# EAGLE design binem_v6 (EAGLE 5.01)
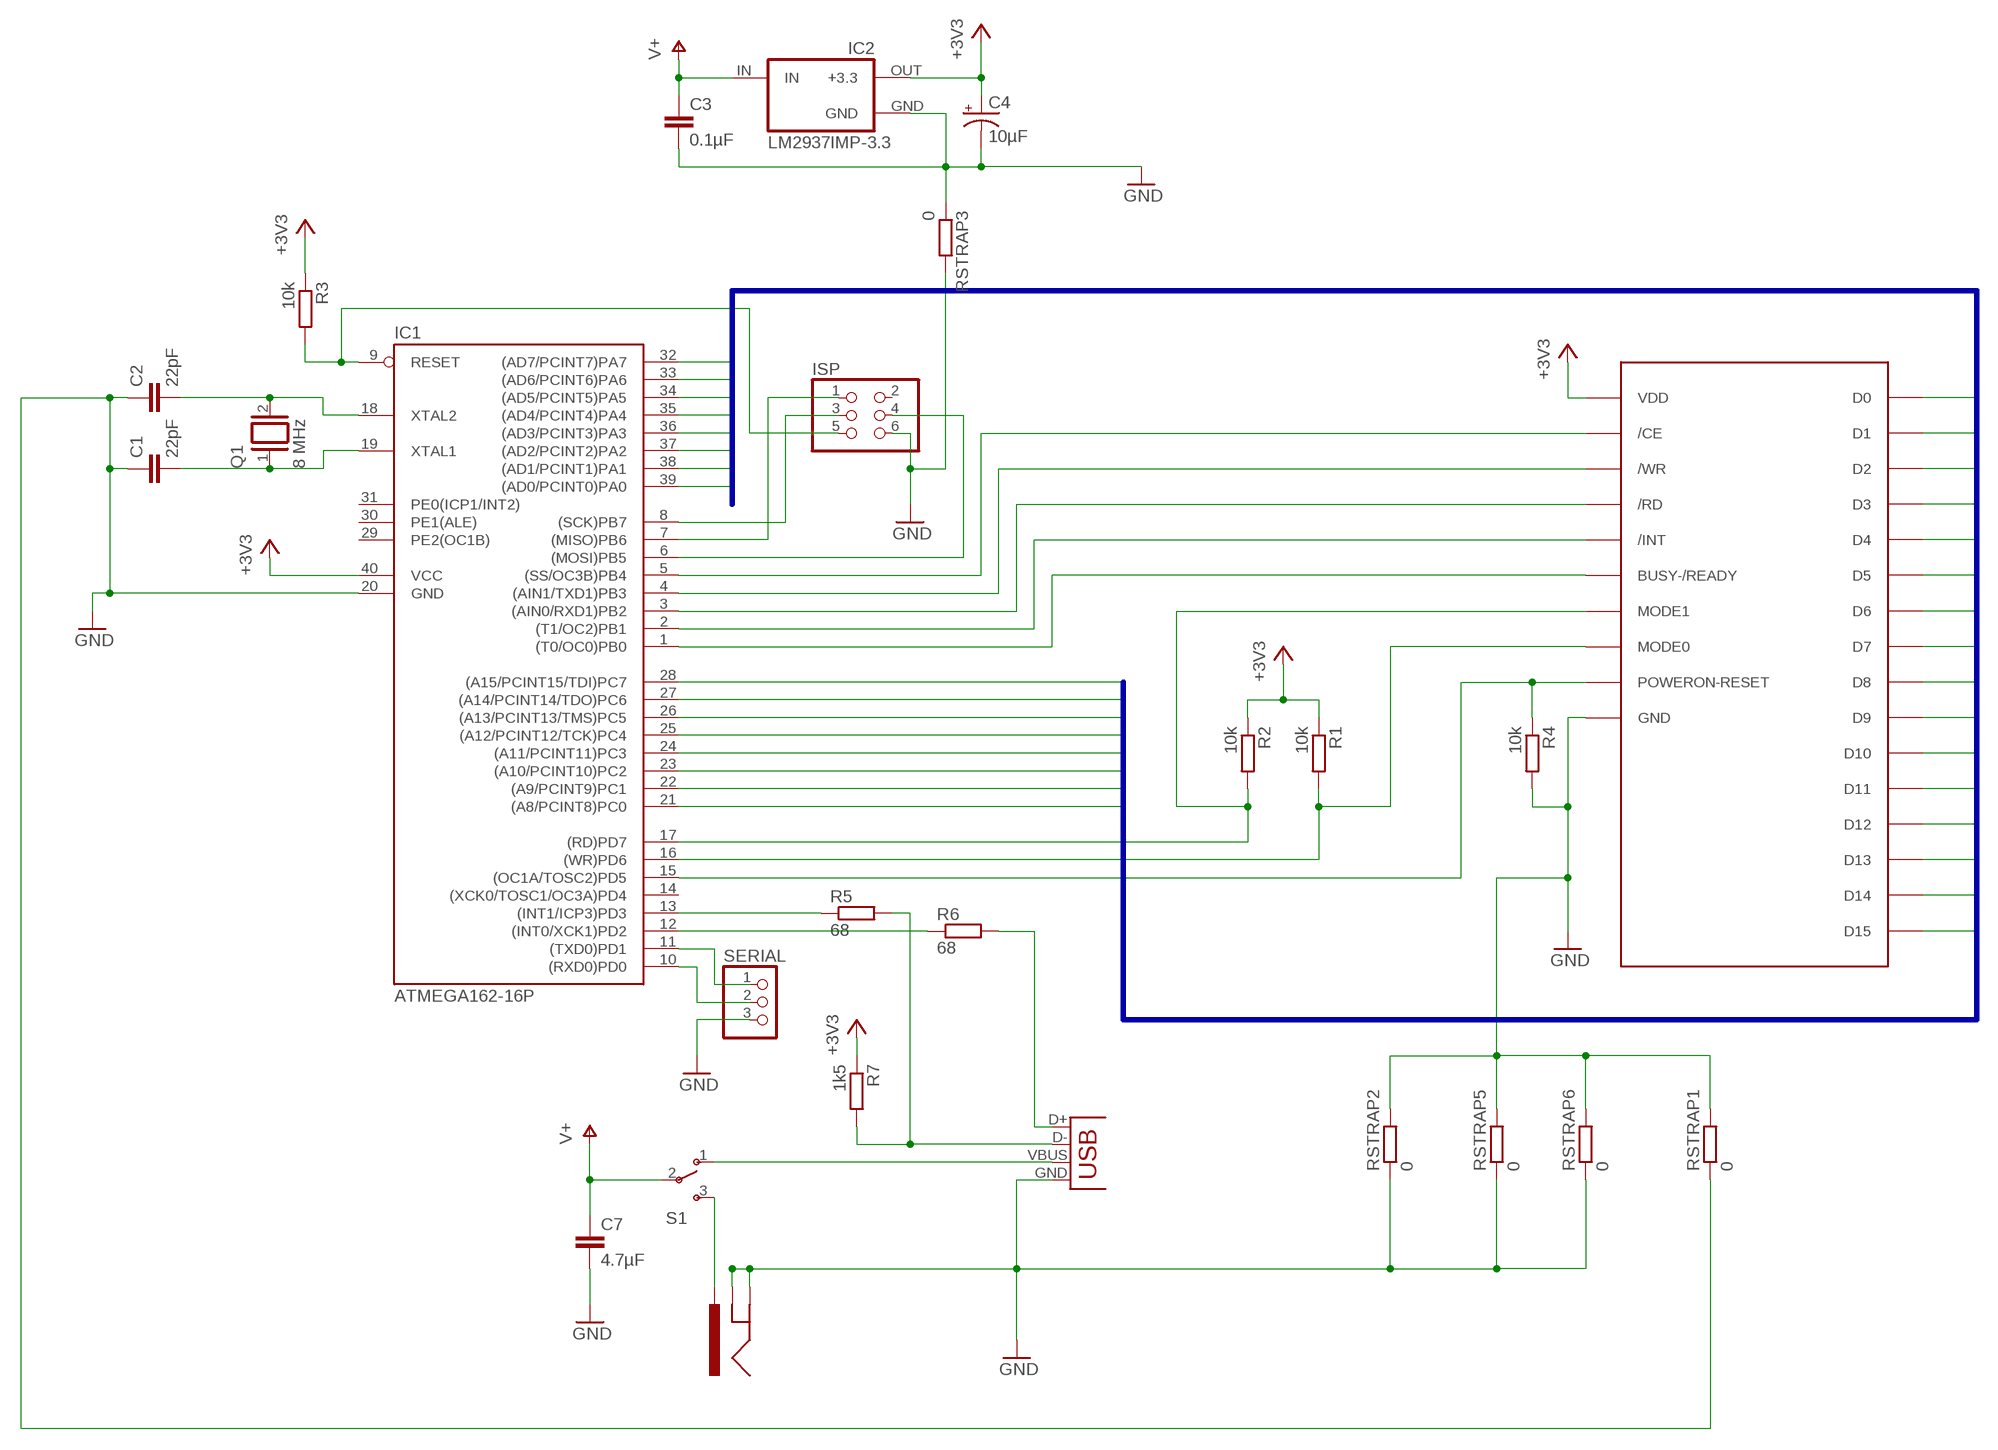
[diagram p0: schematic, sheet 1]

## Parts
C1  22pF  C-EUC1206  [C1206]
C2  22pF  C-EUC1206  [C1206]
C3  0.1µF  C-EUC1206  [C1206]
C4  10µF  CPOL-US175TMP-0808  [175TMP-0808]
C7  4.7µF  C-EUC1206  [C1206]
IC1  ATMEGA162-16P  [DIL40]
IC2  LM2937IMP-3.3  [SOT223]
ISP  PINHD-2X3  [2X03]
Q1  8 MHz  XTAL/S  [QS]
R1  10k  R-EU_R1206  [R1206]
R2  10k  R-EU_R1206  [R1206]
R3  10k  R-EU_R1206  [R1206]
R4  10k  R-EU_R1206  [R1206]
R5  68  R-EU_R1206  [R1206]
R6  68  R-EU_R1206  [R1206]
R7  1k5  R-EU_R1206  [R1206]
RSTRAP1  0  R-EU_R1206  [R1206]
RSTRAP2  0  R-EU_R1206  [R1206]
RSTRAP3  0  R-EU_R1206  [R1206]
RSTRAP5  0  R-EU_R1206  [R1206]
RSTRAP6  0  R-EU_R1206  [R1206]
S1  SWITCH-SPST  [SWITCH-SPST]
SERIAL  PINHD-1X3  [1X03]
U$1  BINEM-BK2300  [MOLEX-522713079]
U$3  POWER_JACKPTH  [POWER_JACK_PTH]
X1  USB  [USB-B-PTH]

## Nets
+3V3: C4.+ IC1.40(VCC) IC2.OUT(+3.3) R1.1 R2.1 R3.1 R7.1 U$1.P$10(VDD)
D0: IC1.39((AD0/PCINT0)PA0) U$1.P$11(D0)
D1: IC1.38((AD1/PCINT1)PA1) U$1.P$12(D1)
D2: IC1.37((AD2/PCINT2)PA2) U$1.P$13(D2)
D3: IC1.36((AD3/PCINT3)PA3) U$1.P$14(D3)
D4: IC1.35((AD4/PCINT4)PA4) U$1.P$15(D4)
D5: IC1.34((AD5/PCINT5)PA5) U$1.P$16(D5)
D6: IC1.33((AD6/PCINT6)PA6) U$1.P$17(D6)
D7: IC1.32((AD7/PCINT7)PA7) U$1.P$18(D7)
D8: IC1.28((A15/PCINT15/TDI)PC7) U$1.P$19(D8)
D9: IC1.27((A14/PCINT14/TDO)PC6) U$1.P$20(D9)
D10: IC1.26((A13/PCINT13/TMS)PC5) U$1.P$21(D10)
D11: IC1.25((A12/PCINT12/TCK)PC4) U$1.P$22(D11)
D12: IC1.24((A11/PCINT11)PC3) U$1.P$23(D12)
D13: IC1.23((A10/PCINT10)PC2) U$1.P$24(D13)
D14: IC1.22((A9/PCINT9)PC1) U$1.P$25(D14)
D15: IC1.21((A8/PCINT8)PC0) U$1.P$26(D15)
GND: C1.1 C2.1 C3.2 C4.- C7.2 IC1.20(GND) IC2.GND ISP.6 R4.2 RSTRAP1.1 RSTRAP1.2 RSTRAP2.1 RSTRAP2.2 RSTRAP3.1 RSTRAP3.2 RSTRAP5.1 RSTRAP5.2 RSTRAP6.1 RSTRAP6.2 SERIAL.3 U$1.P$1(GND) U$3.GND U$3.GNDBREAK X1.GND
MISO: IC1.7((MISO)PB6) ISP.1
MODE0: IC1.16((WR)PD6) R1.2 U$1.P$8(MODE0)
MODE1: IC1.17((RD)PD7) R2.2 U$1.P$7(MODE1)
MOSI: IC1.6((MOSI)PB5) ISP.4
N$1: IC1.13((INT1/ICP3)PD3) R5.1
N$2: R5.2 R7.2 X1.D-
N$3: IC1.12((INT0/XCK1)PD2) R6.1
N$4: R6.2 X1.D+
N$6: S1.3(S) U$3.PWR
N$7: IC1.5((SS/OC3B)PB4) U$1.P$2(/CE)
N$8: IC1.4((AIN1/TXD1)PB3) U$1.P$3(/WR)
N$9: IC1.3((AIN0/RXD1)PB2) U$1.P$4(/RD)
N$10: IC1.2((T1/OC2)PB1) U$1.P$5(/INT)
N$11: IC1.1((T0/OC0)PB0) U$1.P$6(BUSY-/READY)
N$12: IC1.10((RXD0)PD0) SERIAL.2
N$14: C2.2 IC1.18(XTAL2) Q1.2
N$15: C1.2 IC1.19(XTAL1) Q1.1
N$17: IC1.11((TXD0)PD1) SERIAL.1
POWERON-RESET: IC1.15((OC1A/TOSC2)PD5) R4.1 U$1.P$9(POWERON-RESET)
RESET: IC1.9(RESET) ISP.5 R3.2
SCK: IC1.8((SCK)PB7) ISP.3
V+: C3.1 C7.1 IC2.IN S1.2(P)
VUSB: S1.1(O) X1.VBUS
Unconnected: IC1.14((XCK0/TOSC1/OC3A)PD4) IC1.29(PE2(OC1B)) IC1.30(PE1(ALE)) IC1.31(PE0(ICP1/INT2)) ISP.2

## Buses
D[0..15]

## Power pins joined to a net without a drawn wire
GND: IC2.GND@(GND)

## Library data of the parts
C1-C3 C7 = rcl:C-EU: CAPACITOR, European symbol
C4 = rcl:CPOL-US: POLARIZED CAPACITOR, American symbol
IC1 = avr:ATMEGA162*P: MIKROCONTROLLER ATmega162 16kB Flash 2kB RAM 2 USARTS ATmega162 = 2,7-5,5V or ATmega162V = 1,8-5,5V
IC2 = lm2937:LM2937IMP-*: 400 and 500 mA Low Dropout Voltage Regulator NATIONAL SEMICONDUCTOR created by Peter.Hofmann@ph-tronic.de 10-2004 Rev.0
ISP = pinhead:PINHD-2X3: PIN HEADER
Q1 = special:XTAL/S: CRYSTAL
R1-R7 RSTRAP1-RSTRAP3 RSTRAP5 RSTRAP6 = rcl:R-EU_: RESISTOR, European symbol
S1 = SparkFunEagle-6-6-07:SWITCH-SPST: SPST Switch Simple slide switch. Spark Fun Electronics SKU : COM-00102
SERIAL = pinhead:PINHD-1X3: PIN HEADER
U$1 = perso:BINEM-BK2300
U$3 = SparkFunEagle-6-6-07:POWER_JACK: Power Jack This is the standard 5.5mm barrel jack for power. The PTH is the most common, proven, reliable, footprint. All others are experimental. The Slot footprint only works if the mill layer is transmitted to the PCB fab house so be warned. Spark Fun Electronics SKU : PRT-00119. Mating wall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
X1 = SparkFunEagle-6-6-07:USB: USB Connectors USB-B-PTH is fully proven SKU : PRT-00139 USB-miniB is fully proven SKU : PRT-00587 USB-A-H is throughly reviewed, but untested. Spark Fun Electronics SKU : PRT-00437 USB-B-SMT is throughly reviewed, but untested. Needs silkscreen touching up. USB-A-S has not been used/tested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

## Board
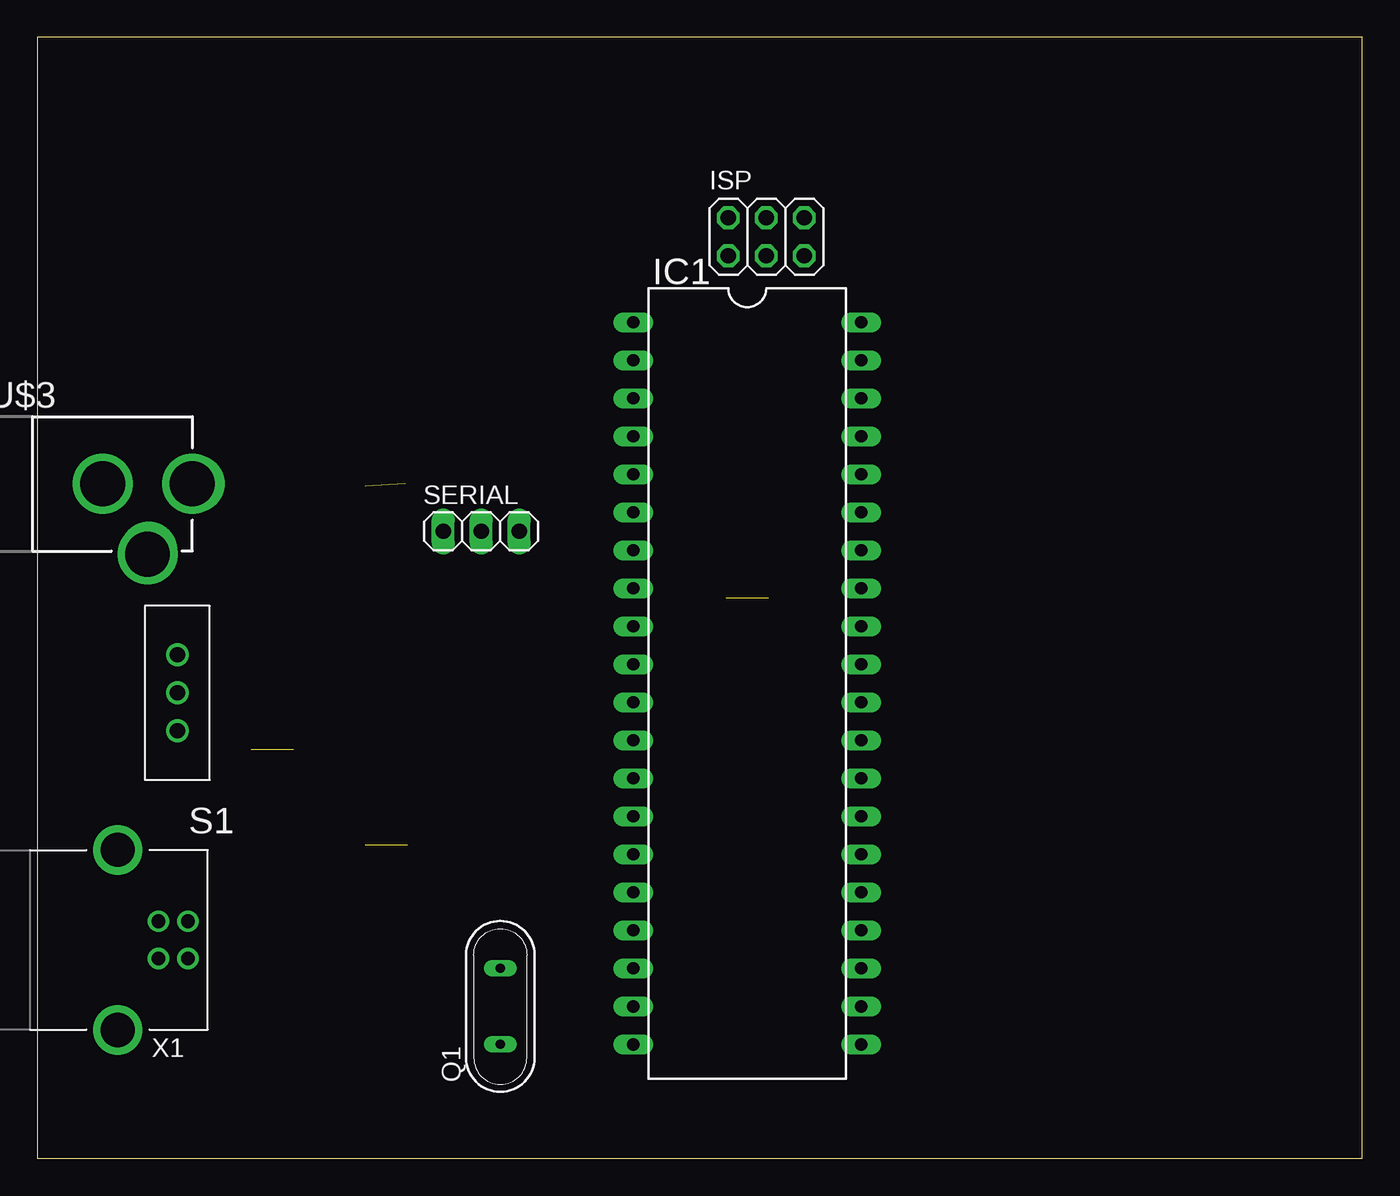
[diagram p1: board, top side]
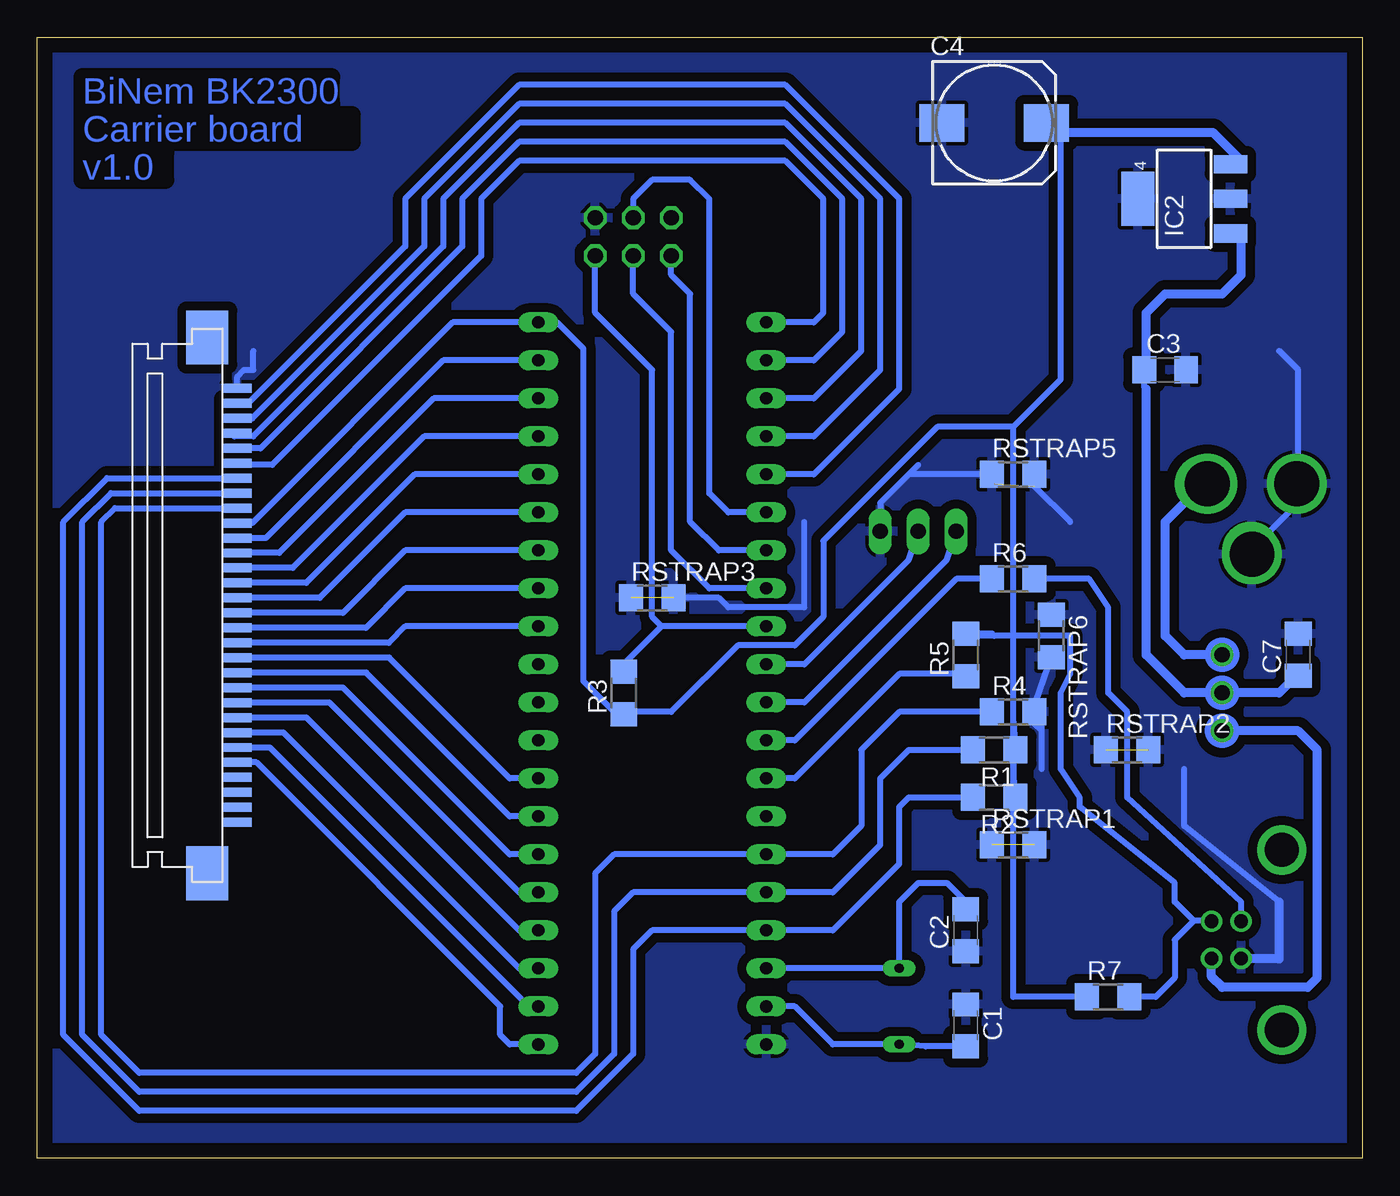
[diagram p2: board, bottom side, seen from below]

Size 88.57 x 74.92 mm. Coordinates in mm from the lower left corner, seen from the top.
Outline: 0,0 88.57,0 88.57,74.92 0,74.92 0,0
Copper layers (1*16): Top 0.035mm / dielectric 1.5mm / Bottom 0.035mm
Design rules "default *": minimum track width 10mil, minimum drill 24mil, track to track 8mil, track to pad 8mil, pad to pad 8mil, via to via 8mil, smd to smd 8mil, copper to edge 40mil, drill to drill 8mil, minimum pad ring 10mil, minimum via ring 8mil, stop-mask expansion 4mil, vias tented up to drill 0mil, thermal gap 10mil

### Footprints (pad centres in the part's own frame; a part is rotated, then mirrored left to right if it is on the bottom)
C1206 = smd 1.6 x 1.8: 1 -1.4,0; 2 1.4,0
175TMP-0808 = smd 3 x 2.5: + 3.5,0; - -3.5,0
DIL40 = drill 0.813 long: 1 -24.13,-7.62; 2 -21.59,-7.62; 3 -19.05,-7.62; 4 -16.51,-7.62; 5 -13.97,-7.62; 6 -11.43,-7.62; 7 -8.89,-7.62; 8 -6.35,-7.62; 9 -3.81,-7.62; 10 -1.27,-7.62; 11 1.27,-7.62; 12 3.81,-7.62; 13 6.35,-7.62; 14 8.89,-7.62; 15 11.43,-7.62; 16 13.97,-7.62; 17 16.51,-7.62; 18 19.05,-7.62; 19 21.59,-7.62; 20 24.13,-7.62; 21 24.13,7.62; 22 21.59,7.62; 23 19.05,7.62; 24 16.51,7.62; 25 13.97,7.62; 26 11.43,7.62; 27 8.89,7.62; 28 6.35,7.62; 29 3.81,7.62; 30 1.27,7.62; 31 -1.27,7.62; 32 -3.81,7.62; 33 -6.35,7.62; 34 -8.89,7.62; 35 -11.43,7.62; 36 -13.97,7.62; 37 -16.51,7.62; 38 -19.05,7.62; 39 -21.59,7.62; 40 -24.13,7.62
SOT223 = smd 1.219 x 2.235: GND 0,-3.099; IN -2.311,-3.099; OUT 2.311,-3.099 | smd 3.6 x 2.2: GND@ 0,3.099
2X03 = drill 1.016 octagon: 1 -2.54,-1.27; 2 -2.54,1.27; 3 0,-1.27; 4 0,1.27; 5 2.54,-1.27; 6 2.54,1.27
QS = drill 0.61 long: 1 -2.54,0; 2 2.54,0
R1206 = smd 1.6 x 1.803: 1 -1.422,0; 2 1.422,0
SWITCH-SPST = drill 1.016 round: 1 0,2.54; 2 0,0; 3 0,-2.54
1X03 = drill 1.016 long: 1 -2.54,0; 2 0,0; 3 2.54,0
MOLEX-522713079 = smd 0.6 x 1.9: P$1 -14,4; P$2 -13,4; P$3 -12,4; P$4 -11,4; P$5 -10,4; P$6 -9,4; P$7 -8,4; P$8 -7,4; P$9 -6,4; P$10 -5,4; P$11 -4,4; P$12 -3,4; P$13 -2,4; P$14 -1,4; P$15 0,4; P$16 1,4; P$17 2,4; P$18 3,4; P$19 4,4; P$20 5,4; P$21 6,4; P$22 7,4; P$23 8,4; P$24 9,4; P$25 10,4; P$26 11,4; P$27 11.99,4.01; P$28 13,4; P$29 14,4; P$30 15,4 | smd 3.6 x 2.8: P$32 18.4,2; P$33 -17.4,2
POWER_JACK_PTH = drill 2.997 round: GND 0,7.7; GNDBREAK 4.7,10.7; PWR 0,13.7
USB-B-PTH = drill 0.914 round: D+ 0,1.25; D- 1.981,1.25; GND 0,-1.25; VBUS 1.981,-1.25 | drill 2.286 round: P$1 -2.718,-6.02; P$2 -2.718,6.02

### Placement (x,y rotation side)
C1  26.5,8.89 270 bottom
C2  26.5,15.24 90 bottom
C3  13.17,52.7 0 bottom
C4  24.6,69.21 0 bottom
C7  4.28,33.65 90 bottom
IC1  47.46,31.74 270 top
IC2  11.9,64.13 90 bottom
ISP  48.73,61.59 0 top
Q1  30.95,10.16 90 top
R1  24.6,27.3 180 bottom
R2  24.6,24.12 180 bottom
R3  49.37,31.11 90 bottom
R4  23.33,29.84 0 bottom
R5  26.5,33.65 90 bottom
R6  23.33,38.73 0 bottom
R7  16.98,10.79 0 bottom
RSTRAP1  23.33,20.95 0 bottom
RSTRAP2  15.71,27.3 0 bottom
RSTRAP3  47.46,37.46 0 bottom
RSTRAP5  23.33,45.72 0 bottom
RSTRAP6  20.79,34.92 270 bottom
S1  9.36,31.11 180 top
SERIAL  29.68,41.91 0 top
U$1  79.21,37.46 270 bottom
U$3  -3.34,45.08 270 top
X1  8.09,14.6 0 top

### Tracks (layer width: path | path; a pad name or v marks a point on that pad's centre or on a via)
+3V3
  Bottom 0.406: R7.1 23.33,10.79 23.33,28.57 | R2.1 23.33,25.39 23.33,28.57 | 23.33,28.57 23.33,48.89 | R1.1 23.33,29.2 23.33,28.57 | C4.+ 20.79,69.21 20.47,68.89 20.15,68.57 20.15,52.07 23.33,48.89 | 8.09,66.67 9.36,66.67 9.13,66.44 IC2.OUT | 23.33,48.89 28.41,48.89 36.03,41.27 36.03,36.19 37.94,34.29 41.74,34.29 46.19,29.84 50,29.84 | 50,29.84 52.06,31.9 52.06,54.12 53.81,55.88 IC1.40 60.8,55.88 74.21,42.46 U$1.P$10 | R3.1 50,29.69 50,29.84
  Bottom 0.61: 8.09,66.67 10,68.57 20.15,68.57 20.79,68.57 20.47,68.89
D0
  Bottom 0.406: U$1.P$11 73.3,41.46 61.43,53.34 IC1.39
D1
  Bottom 0.406: U$1.P$12 72.4,40.46 62.06,50.8 IC1.38
D2
  Bottom 0.406: U$1.P$13 71.5,39.46 62.7,48.26 IC1.37
D3
  Bottom 0.406: U$1.P$14 70.59,38.46 63.34,45.72 IC1.36
D4
  Bottom 0.406: U$1.P$15 69.69,37.46 63.97,43.18 IC1.35
D5
  Bottom 0.406: U$1.P$16 68.14,36.46 63.97,40.64 IC1.34
D6
  Bottom 0.406: U$1.P$17 66.61,35.46 63.97,38.1 IC1.33
D7
  Bottom 0.406: U$1.P$18 65.06,34.46 63.97,35.55 IC1.32
D8
  Bottom 0.406: U$1.P$19 65.05,33.46 56.98,25.39 IC1.28
D9
  Bottom 0.406: U$1.P$20 66.59,32.46 56.98,22.86 IC1.27
D10
  Bottom 0.406: U$1.P$21 68.13,31.46 56.98,20.31 IC1.26
D11
  Bottom 0.406: U$1.P$22 69.03,30.46 56.35,17.77 IC1.25
D12
  Bottom 0.406: U$1.P$23 70.58,29.46 56.35,15.24 IC1.24
D13
  Bottom 0.406: U$1.P$24 72.11,28.46 56.35,12.7 IC1.23
D14
  Bottom 0.406: U$1.P$25 73.02,27.46 55.71,10.16 IC1.22
D15
  Bottom 0.406: U$1.P$26 73.92,26.46 57.62,10.16 57.62,8.25 56.98,7.62 IC1.21
GND  (via drill 1 pad 3.81)  (4 unrouted)
  Bottom 0.406: 5.55,53.97 4.28,52.7 v4.28,45.08 U$3.GND 4.36,43.73 v7.46,40.64 | 5.55,17.14 11.9,22.22 11.9,26.03 | RSTRAP5.2 21.91,44.93 19.52,42.54 | 21.42,26.03 21.42,28.57 | 21.42,28.57 21.42,29.2 | RSTRAP6.2 22.06,29.84 R4.2 21.91,29.05 21.42,28.57 | SERIAL.3 32.22,43.81 30.31,45.72 | 30.31,45.72 29.68,46.35 | RSTRAP3.2 43.02,37.46 42.38,36.83 37.3,36.83 37.3,42.54 | U$1.P$1 75.21,52.26 74.77,52.7 74.13,52.7 74.13,53.97 | 24.6,45.08 24.75,45.23 RSTRAP5.1 30.31,45.72
  Bottom 0.61: X1.GND 8.07,13.33 5.55,13.33 5.55,17.14
  pour Bottom (isolate 0.61): 0.47,74.29 88.1,74.29 88.1,0.63 0.47,0.63
MISO
  Bottom 0.406: ISP.1 46.19,59.05 44.92,57.78 44.92,42.54 43.02,40.64 IC1.7
MODE0
  Bottom 0.406: U$1.P$8 83.64,44.46 85.56,42.54 85.56,8.25 81.75,4.44 52.54,4.44 50,6.98 50,16.5 48.73,17.77 IC1.16 35.39,17.77 32.22,20.95 32.22,25.39 30.31,27.3 R1.2
MODE1
  Bottom 0.406: U$1.P$7 83.91,45.46 86.83,42.54 86.83,8.25 81.75,3.17 52.54,3.17 48.73,6.98 48.73,13.97 47.46,15.24 IC1.17 35.39,15.24 30.95,19.68 30.95,23.49 30.31,24.12 R2.2
MOSI
  Bottom 0.406: ISP.4 48.73,64.13 47.46,65.4 44.92,65.4 43.65,64.13 43.65,44.45 42.38,43.18 IC1.6
N$1
  Bottom 0.406: IC1.13 37.94,25.39 30.95,32.38 26.5,32.38 R5.1
N$2
  Bottom 0.406: X1.D- 10.09,15.87 11.27,15.87 | 11.27,15.87 12.54,14.6 12.54,12.06 13.81,10.79 R7.2 | 11.27,15.87 12.54,17.14 12.54,18.41 18.88,23.49 18.88,24.12 20.15,26.03 20.15,31.11 19.52,32.38 19.52,34.92 24.6,34.92 | 24.6,34.92 25.87,34.92 | R5.2 24.75,35.07 24.6,34.92
N$3
  Bottom 0.406: R6.1 27.14,38.73 37.94,27.93 IC1.12
N$4
  Bottom 0.406: X1.D+ 8.09,17.14 15.71,24.12 15.71,29.84 16.98,31.11 16.98,36.83 18.25,38.73 R6.2
N$5  (via drill 1 pad 3.81)
  other vias: 10.63,45.08
N$6
  Bottom 0.61: S1.3 11.9,33.65 13.17,34.92 13.17,42.54 10.63,45.08 U$3.PWR
N$7
  Bottom 0.406: IC1.5 36.66,45.72 30.95,51.43 30.95,64.13 38.57,71.75 56.35,71.75 63.97,64.13 63.97,60.96 74.47,50.46 U$1.P$2
N$8
  Bottom 0.406: IC1.4 36.66,48.26 32.22,52.7 32.22,64.13 38.57,70.48 56.35,70.48 62.7,64.13 62.7,60.96 74.19,49.46 U$1.P$3
N$9
  Bottom 0.406: IC1.3 36.66,50.8 33.49,53.97 33.49,64.13 38.57,69.21 56.35,69.21 61.43,64.13 61.43,60.96 74.13,48.26 75.4,48.26 75.21,48.45 U$1.P$4
N$10
  Bottom 0.406: IC1.2 36.66,53.34 34.76,55.24 34.76,64.13 38.57,67.94 56.35,67.94 60.16,64.13 60.16,60.96 73.66,47.46 U$1.P$5
N$11
  Bottom 0.406: IC1.1 36.66,55.88 36.03,56.51 36.03,64.13 38.57,66.67 56.35,66.67 58.89,64.13 58.89,60.32 72.86,46.35 75.4,46.35 75.29,46.46 U$1.P$6
N$12
  Bottom 0.406: SERIAL.2 30.31,40 37.3,33.02 IC1.10
N$14
  Bottom 0.406: IC1.18 Q1.2 30.95,17.14 29.68,18.41 27.77,18.41 26.5,17.14 C2.2
N$15
  Bottom 0.406: IC1.19 37.94,10.16 35.39,7.62 Q1.1 29.17,7.49 C1.2
N$17
  Bottom 0.406: IC1.11 37.3,30.47 27.77,40 SERIAL.1
POWERON-RESET
  Bottom 0.406: U$1.P$9 83.37,43.46 84.29,42.54 84.29,8.25 81.75,5.71 52.54,5.71 51.27,6.98 51.27,19.04 50,20.31 IC1.15 35.39,20.31 33.49,22.22 33.49,27.3 30.95,29.84 R4.1
RESET
  Bottom 0.406: ISP.5 51.27,56.51 47.46,52.7 47.46,36.19 46.82,35.55 | IC1.9 46.82,35.55 | 46.82,35.55 50,32.38 50,32.53 R3.2
SCK
  Bottom 0.406: ISP.3 48.73,57.78 46.19,55.24 46.19,40.64 43.65,38.1 IC1.8
V+
  Bottom 0.406: 8.09,61.59 9.36,61.59 9.13,61.82 IC2.IN | 14.44,51.43 14.57,51.56 C3.1 14.44,52.7
  Bottom 0.61: 14.44,51.43 14.44,33.65 11.9,31.11 S1.2 5.55,31.11 4.28,32.38 C7.1 | 14.44,52.7 14.44,56.51 13.17,57.78 9.36,57.78 8.09,59.05 8.09,61.59
VUSB
  Bottom 0.61: X1.VBUS 10.07,12.14 9.36,11.43 3.64,11.43 3.01,12.06 3.01,27.3 4.28,28.57 S1.1
(copper drawn outside any net)
  shapes: Bottom circle x3

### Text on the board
Bottom: BiNem BK2300 | Carrier board | v1.0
